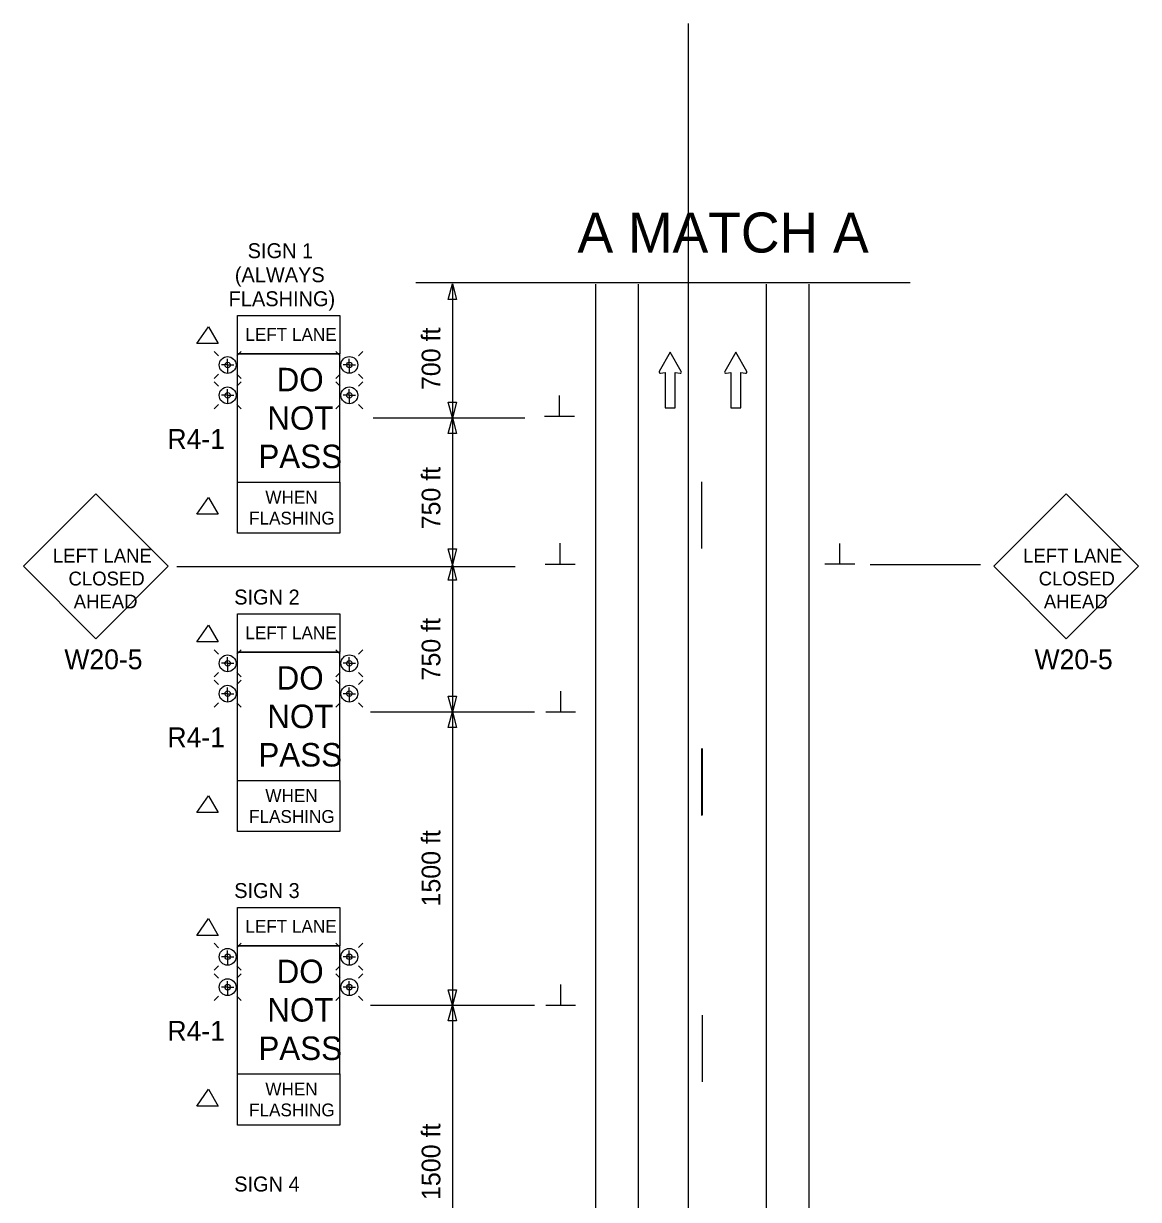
# Model space of a CAD drawing. Extents: x 15277 to 18126, y 1908 to 6555.
# Drawn here: x 16361.8 to 16779.9, y 2795.7 to 3236.5 of the extents above; entities that cross this region are included whole.
import ezdxf

# ---------------------------------------------------------------- set-up
doc = ezdxf.new("R2010")
doc.units = 0
for name, color, linetype in [('ALI_LEGAL_EX', 7, 'Continuous'), ('MT_SCRATCH_LEVEL_E', 7, 'Continuous'), ('PAVT_EDGE_EX', 7, 'Continuous'), ('TRAFFIC_SIGNS_PR', 7, 'Continuous'), ('TYPICAL_TEXT_DIMEN_PR', 7, 'Continuous')]:
    doc.layers.add(name, color=color, linetype=linetype)

msp = doc.modelspace()

# ---------------------------------------------------------------- linework, layer by layer
at = {"layer": 'ALI_LEGAL_EX'}
msp.add_line((16610.98, 3236.46), (16610.98, 2407.28), dxfattribs=at)
for points in [[(16616.07, 3064.67), (16616.07, 3039.67)], [(16616.07, 2964.67), (16616.07, 2939.67)], [(16616.35, 2964.74), (16616.35, 2939.74)], [(16616.35, 2864.74), (16616.35, 2839.74)]]:
    msp.add_lwpolyline(points, dxfattribs=at)
at = {"layer": 'MT_SCRATCH_LEVEL_E'}
for p, q in [((16604.32, 3113.3), (16600.21, 3106.06)), ((16608.47, 3106.06), (16604.32, 3113.3)), ((16628.88, 3113.3), (16624.77, 3106.06)), ((16633.03, 3106.06), (16628.88, 3113.3)), ((16600.69, 3105.38), (16602.47, 3105.69)), ((16602.47, 3105.69), (16602.47, 3092.43)), ((16606.21, 3092.43), (16606.21, 3105.69)), ((16606.21, 3105.69), (16607.99, 3105.38)), ((16625.25, 3105.38), (16627.03, 3105.69)), ((16627.03, 3105.69), (16627.03, 3092.43)), ((16630.77, 3092.43), (16630.77, 3105.69)), ((16630.77, 3105.69), (16632.55, 3105.38)), ((16602.47, 3092.43), (16606.21, 3092.43)), ((16627.03, 3092.43), (16630.77, 3092.43))]:
    msp.add_line(p, q, dxfattribs=at)
for centre, start, end in [((16600.62, 3105.84), 150.4248, 279.9638), ((16608.06, 3105.84), 260.0362, 29.7731), ((16625.17, 3105.84), 150.4248, 279.9638), ((16632.62, 3105.84), 260.0362, 29.7731)]:
    msp.add_arc(centre, 0.463, start, end, dxfattribs=at)
at = {"layer": 'PAVT_EDGE_EX'}
for p, q in [((16576.35, 3138.78), (16576.35, 2305.55)), ((16592.35, 3138.78), (16592.35, 2305.55)), ((16640.35, 3138.78), (16640.35, 2305.55)), ((16656.35, 3138.78), (16656.35, 2305.55))]:
    msp.add_line(p, q, dxfattribs=at)
at = {"layer": 'TRAFFIC_SIGNS_PR'}
for p, q in [((16434.9, 3111.91), (16433.27, 3113.53)), ((16441.74, 3111.91), (16443.37, 3113.53)), ((16442.06, 3064.61), (16442.06, 3112.61)), ((16442.06, 3112.61), (16480.46, 3112.61)), ((16480.54, 3111.92), (16478.91, 3113.55)), ((16480.46, 3064.61), (16480.46, 3112.61)), ((16487.39, 3111.92), (16489.02, 3113.55)), ((16438.32, 3108.48), (16436.02, 3108.48)), ((16438.32, 3108.48), (16438.32, 3110.78)), ((16438.32, 3108.48), (16438.32, 3105.33)), ((16438.32, 3108.48), (16440.62, 3108.48)), ((16483.96, 3108.5), (16481.66, 3108.5)), ((16483.96, 3108.5), (16483.96, 3110.8)), ((16483.96, 3108.5), (16483.96, 3105.35)), ((16483.96, 3108.5), (16486.27, 3108.5)), ((16434.9, 3105.06), (16433.27, 3103.43)), ((16443.37, 3103.43), (16441.74, 3105.06)), ((16480.54, 3105.07), (16478.91, 3103.45)), ((16489.01, 3103.45), (16487.39, 3105.07)), ((16434.9, 3100.53), (16433.27, 3102.16)), ((16438.32, 3097.11), (16438.32, 3099.41)), ((16441.74, 3100.53), (16443.37, 3102.16)), ((16480.54, 3100.53), (16478.91, 3102.16)), ((16483.96, 3097.11), (16483.96, 3099.41)), ((16487.39, 3100.53), (16489.02, 3102.16)), ((16438.32, 3097.11), (16436.02, 3097.11)), ((16438.32, 3097.11), (16438.32, 3093.96)), ((16438.32, 3097.11), (16440.62, 3097.11)), ((16483.96, 3097.11), (16481.66, 3097.11)), ((16483.96, 3097.11), (16483.96, 3093.96)), ((16483.96, 3097.11), (16486.27, 3097.11)), ((16434.9, 3093.68), (16433.27, 3092.06)), ((16443.37, 3092.06), (16441.74, 3093.68)), ((16480.54, 3093.68), (16478.91, 3092.06)), ((16489.01, 3092.06), (16487.39, 3093.68)), ((16442.06, 3064.61), (16480.46, 3064.61)), ((16388.92, 3060.19), (16361.77, 3033.04)), ((16416.08, 3033.04), (16388.92, 3060.19)), ((16752.78, 3060.19), (16725.62, 3033.04)), ((16779.93, 3033.04), (16752.78, 3060.19)), ((16361.77, 3033.04), (16388.92, 3005.88)), ((16388.92, 3005.88), (16416.08, 3033.04)), ((16725.62, 3033.04), (16752.78, 3005.88)), ((16752.78, 3005.88), (16779.93, 3033.04)), ((16434.9, 3000.08), (16433.27, 3001.71)), ((16441.74, 3000.08), (16443.37, 3001.71)), ((16480.54, 3000.1), (16478.91, 3001.72)), ((16487.39, 3000.1), (16489.02, 3001.72)), ((16438.32, 2996.66), (16438.32, 2998.96)), ((16442.06, 2952.78), (16442.06, 3000.78)), ((16442.06, 3000.78), (16480.46, 3000.78)), ((16480.46, 2952.78), (16480.46, 3000.78)), ((16483.96, 2996.67), (16483.96, 2998.97)), ((16434.9, 2993.23), (16433.27, 2991.6)), ((16438.32, 2996.66), (16436.02, 2996.66)), ((16438.32, 2996.66), (16438.32, 2993.51)), ((16438.32, 2996.66), (16440.62, 2996.66)), ((16443.37, 2991.6), (16441.74, 2993.23)), ((16480.54, 2993.25), (16478.91, 2991.62)), ((16483.96, 2996.67), (16481.66, 2996.67)), ((16483.96, 2996.67), (16483.96, 2993.52)), ((16483.96, 2996.67), (16486.27, 2996.67)), ((16489.01, 2991.62), (16487.39, 2993.25)), ((16434.9, 2988.71), (16433.27, 2990.33)), ((16441.74, 2988.7), (16443.37, 2990.33)), ((16480.54, 2988.71), (16478.91, 2990.33)), ((16487.39, 2988.7), (16489.02, 2990.33)), ((16438.32, 2985.28), (16436.02, 2985.28)), ((16438.32, 2985.28), (16438.32, 2987.58)), ((16438.32, 2985.28), (16438.32, 2982.13)), ((16438.32, 2985.28), (16440.62, 2985.28)), ((16483.96, 2985.28), (16481.66, 2985.28)), ((16483.96, 2985.28), (16483.96, 2987.58)), ((16483.96, 2985.28), (16483.96, 2982.13)), ((16483.96, 2985.28), (16486.27, 2985.28)), ((16434.9, 2981.86), (16433.27, 2980.23)), ((16443.37, 2980.23), (16441.74, 2981.86)), ((16480.54, 2981.86), (16478.91, 2980.23)), ((16489.01, 2980.23), (16487.39, 2981.86)), ((16442.06, 2952.78), (16480.46, 2952.78)), ((16434.9, 2890.08), (16433.27, 2891.71)), ((16441.74, 2890.08), (16443.37, 2891.71)), ((16480.54, 2890.1), (16478.91, 2891.72)), ((16487.39, 2890.1), (16489.02, 2891.72)), ((16438.32, 2886.66), (16438.32, 2888.96)), ((16442.06, 2842.78), (16442.06, 2890.78)), ((16442.06, 2890.78), (16480.46, 2890.78)), ((16480.46, 2842.78), (16480.46, 2890.78)), ((16483.96, 2886.67), (16483.96, 2888.97)), ((16434.9, 2883.23), (16433.27, 2881.6)), ((16438.32, 2886.66), (16436.02, 2886.66)), ((16438.32, 2886.66), (16438.32, 2883.51)), ((16438.32, 2886.66), (16440.62, 2886.66)), ((16443.37, 2881.6), (16441.74, 2883.23)), ((16480.54, 2883.25), (16478.91, 2881.62)), ((16483.96, 2886.67), (16481.66, 2886.67)), ((16483.96, 2886.67), (16483.96, 2883.52)), ((16483.96, 2886.67), (16486.27, 2886.67)), ((16489.01, 2881.62), (16487.39, 2883.25)), ((16434.9, 2878.71), (16433.27, 2880.33)), ((16441.74, 2878.7), (16443.37, 2880.33)), ((16480.54, 2878.71), (16478.91, 2880.33)), ((16487.39, 2878.7), (16489.02, 2880.33)), ((16438.32, 2875.28), (16436.02, 2875.28)), ((16438.32, 2875.28), (16438.32, 2877.58)), ((16438.32, 2875.28), (16438.32, 2872.13)), ((16438.32, 2875.28), (16440.62, 2875.28)), ((16483.96, 2875.28), (16481.66, 2875.28)), ((16483.96, 2875.28), (16483.96, 2877.58)), ((16483.96, 2875.28), (16483.96, 2872.13)), ((16483.96, 2875.28), (16486.27, 2875.28)), ((16434.9, 2871.86), (16433.27, 2870.23)), ((16443.37, 2870.23), (16441.74, 2871.86)), ((16480.54, 2871.86), (16478.91, 2870.23)), ((16489.01, 2870.23), (16487.39, 2871.86)), ((16442.06, 2842.78), (16480.46, 2842.78))]:
    msp.add_line(p, q, dxfattribs=at)
for centre, radius in [((16438.32, 3108.48), 3.15), ((16438.32, 3108.48), 1.02), ((16483.96, 3108.5), 3.15), ((16483.96, 3108.5), 1.02), ((16438.32, 3097.11), 3.15), ((16483.96, 3097.11), 3.15), ((16438.32, 3097.11), 1.02), ((16483.96, 3097.11), 1.02), ((16438.32, 2996.65), 3.15), ((16438.32, 2996.65), 1.02), ((16483.96, 2996.67), 3.15), ((16483.96, 2996.67), 1.02), ((16438.32, 2985.28), 3.15), ((16483.96, 2985.28), 3.15), ((16438.32, 2985.28), 1.02), ((16483.96, 2985.28), 1.02), ((16438.32, 2886.65), 3.15), ((16438.32, 2886.65), 1.02), ((16483.96, 2886.67), 3.15), ((16483.96, 2886.67), 1.02), ((16438.32, 2875.28), 3.15), ((16483.96, 2875.28), 3.15), ((16438.32, 2875.28), 1.02), ((16483.96, 2875.28), 1.02)]:
    msp.add_circle(centre, radius, dxfattribs=at)
at = {"layer": 'TYPICAL_TEXT_DIMEN_PR'}
for p, q in [((16508.93, 3139.37), (16694.24, 3139.37)), ((16521.05, 3133.07), (16522.62, 3138.93)), ((16522.62, 3138.93), (16524.19, 3133.07)), ((16522.62, 3138.65), (16522.62, 3068.65)), ((16522.62, 3133.07), (16521.05, 3133.07)), ((16524.19, 3133.07), (16522.62, 3133.07)), ((16522.62, 3088.64), (16521.05, 3094.51)), ((16521.05, 3094.51), (16522.62, 3094.51)), ((16522.62, 3094.51), (16524.19, 3094.51)), ((16524.19, 3094.51), (16522.62, 3088.64)), ((16562.78, 3089.31), (16562.78, 3097.09)), ((16492.95, 3088.64), (16549.74, 3088.64)), ((16521.05, 3082.78), (16522.62, 3088.64)), ((16522.62, 3088.64), (16522.62, 3018.64)), ((16522.62, 3088.64), (16524.19, 3082.78)), ((16557.15, 3089.31), (16568.4, 3089.31)), ((16522.62, 3082.78), (16521.05, 3082.78)), ((16524.19, 3082.78), (16522.62, 3082.78)), ((16563, 3033.88), (16563, 3041.66)), ((16667.92, 3033.77), (16667.92, 3041.56)), ((16522.62, 3033.66), (16521.06, 3039.53)), ((16521.06, 3039.53), (16522.62, 3039.53)), ((16522.62, 3039.53), (16524.19, 3039.53)), ((16524.19, 3039.53), (16522.62, 3033.66)), ((16419.26, 3032.92), (16546.13, 3032.92)), ((16521.05, 3027.82), (16522.62, 3033.68)), ((16522.62, 3033.68), (16524.19, 3027.82)), ((16522.62, 3033.48), (16522.62, 2963.48)), ((16557.38, 3033.88), (16568.62, 3033.88)), ((16673.55, 3033.77), (16662.3, 3033.77)), ((16720.72, 3033.52), (16679.35, 3033.52)), ((16522.62, 3027.82), (16521.05, 3027.82)), ((16524.19, 3027.82), (16522.62, 3027.82)), ((16522.62, 2978.48), (16521.06, 2984.34)), ((16521.06, 2984.34), (16522.62, 2984.34)), ((16522.62, 2988.35), (16522.62, 2984.58)), ((16522.62, 2984.34), (16524.19, 2984.34)), ((16524.19, 2984.34), (16522.62, 2978.48)), ((16563.23, 2978.48), (16563.23, 2986.26)), ((16491.89, 2978.48), (16553.35, 2978.48)), ((16521.06, 2972.61), (16522.62, 2978.48)), ((16522.62, 2978.48), (16522.62, 2868.48)), ((16522.62, 2978.48), (16524.19, 2972.61)), ((16557.6, 2978.48), (16568.85, 2978.48)), ((16522.62, 2972.61), (16521.06, 2972.61)), ((16524.19, 2972.61), (16522.62, 2972.61)), ((16522.62, 2868.48), (16521.06, 2874.34)), ((16521.06, 2874.34), (16522.62, 2874.34)), ((16522.62, 2874.34), (16524.19, 2874.34)), ((16524.19, 2874.34), (16522.62, 2868.48)), ((16563.23, 2868.48), (16563.23, 2876.26)), ((16491.89, 2868.48), (16553.35, 2868.48)), ((16521.06, 2862.61), (16522.62, 2868.48)), ((16522.62, 2868.48), (16522.62, 2758.48)), ((16522.62, 2868.48), (16524.19, 2862.61)), ((16557.6, 2868.48), (16568.85, 2868.48)), ((16522.62, 2862.61), (16521.06, 2862.61)), ((16524.19, 2862.61), (16522.62, 2862.61))]:
    msp.add_line(p, q, dxfattribs=at)
for points in [[(16442.06, 3127), (16480.46, 3127), (16480.46, 3112.61), (16442.06, 3112.61)], [(16426.76, 3116.5), (16431.12, 3122.8), (16434.83, 3116.5)], [(16442.06, 3064.61), (16480.46, 3064.61), (16480.46, 3045.41), (16442.06, 3045.41)], [(16426.76, 3052.53), (16431.12, 3058.83), (16434.83, 3052.53)], [(16442.06, 3015.18), (16480.46, 3015.18), (16480.46, 3000.78), (16442.06, 3000.78)], [(16426.76, 3004.67), (16431.12, 3010.97), (16434.83, 3004.67)], [(16442.06, 2952.78), (16480.46, 2952.78), (16480.46, 2933.59), (16442.06, 2933.59)], [(16426.76, 2940.7), (16431.12, 2947.01), (16434.83, 2940.7)], [(16442.06, 2905.18), (16480.46, 2905.18), (16480.46, 2890.78), (16442.06, 2890.78)], [(16426.76, 2894.67), (16431.12, 2900.97), (16434.83, 2894.67)], [(16442.06, 2842.78), (16480.46, 2842.78), (16480.46, 2823.59), (16442.06, 2823.59)], [(16426.76, 2830.7), (16431.12, 2837.01), (16434.83, 2830.7)]]:
    msp.add_lwpolyline(points, close=True, dxfattribs=at)

# ---------------------------------------------------------------- texts
at = {"layer": 'TRAFFIC_SIGNS_PR'}
for s, height, p in [('DO', 8.8, (16456.69, 3098.61)), ('NOT', 8.8, (16453.2, 3084.21)), ('R4-1', 7.44, (16415.74, 3077.03)), ('PASS', 8.8, (16449.85, 3069.81)), ('LEFT LANE', 5.2, (16372.8, 3034.43)), ('LEFT LANE', 5.2, (16736.66, 3034.43)), ('CLOSED', 5.2, (16378.64, 3025.83)), ('CLOSED', 5.2, (16742.49, 3025.83)), ('AHEAD', 5.2, (16380.58, 3017.23)), ('AHEAD', 5.2, (16744.43, 3017.23)), ('W20-5', 7.44, (16377.1, 2994.44)), ('W20-5', 7.44, (16740.95, 2994.44)), ('DO', 8.8, (16456.69, 2986.78)), ('NOT', 8.8, (16453.2, 2972.38)), ('R4-1', 7.44, (16415.74, 2965.2)), ('PASS', 8.8, (16449.85, 2957.98)), ('DO', 8.8, (16456.69, 2876.78)), ('NOT', 8.8, (16453.2, 2862.38)), ('R4-1', 7.44, (16415.74, 2855.2)), ('PASS', 8.8, (16449.85, 2847.98))]:
    msp.add_text(s, height=height, dxfattribs=at).set_placement(p)
at = {"layer": 'TYPICAL_TEXT_DIMEN_PR'}
for s, height, p in [('A MATCH A', 15, (16569.53, 3150.62)), (' SIGN 1 ', 5.6, (16443.76, 3148.51)), ('  (ALWAYS  ', 5.6, (16436.86, 3139.51)), ('  FLASHING) ', 5.6, (16434.55, 3130.51)), ('LEFT LANE', 4.8, (16444.98, 3117.51)), ('WHEN', 4.8, (16452.48, 3056.52)), ('FLASHING', 4.8, (16446.37, 3048.68)), ('   SIGN 2   ', 5.6, (16434.55, 3018.69)), ('LEFT LANE', 4.8, (16444.98, 3005.69)), ('WHEN', 4.8, (16452.48, 2944.69)), ('FLASHING', 4.8, (16446.37, 2936.86)), ('   SIGN 3   ', 5.6, (16434.56, 2908.69)), ('LEFT LANE', 4.8, (16444.98, 2895.69)), ('WHEN', 4.8, (16452.48, 2834.69)), ('FLASHING', 4.8, (16446.37, 2826.86)), ('   SIGN 4   ', 5.6, (16434.55, 2798.69))]:
    msp.add_text(s, height=height, dxfattribs=at).set_placement(p)
for s, p in [('700 ft', (16518.1, 3099.07)), ('750 ft', (16518.1, 3046.88)), ('750 ft', (16518.1, 2990.23)), ('1500 ft', (16518.1, 2905.51)), ('1500 ft', (16518.1, 2795.51))]:
    msp.add_text(s, height=7, rotation=90, dxfattribs=at).set_placement(p)

doc.saveas('drawing.dxf')
